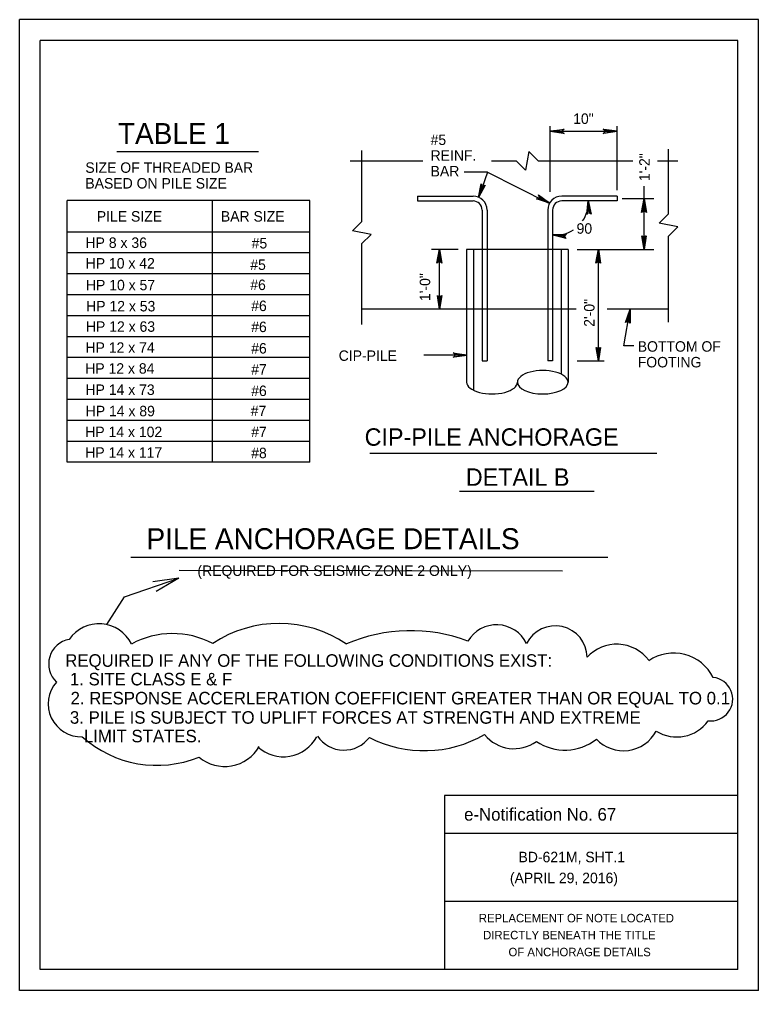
# Model space of a CAD drawing. Extents: x 235 to 2276, y 116 to 1308.
# Drawn here: x 274.6 to 486.6, y 1029.5 to 1307.9 of the extents above; entities that cross this region are included whole.
import ezdxf

# ---------------------------------------------------------------- set-up
doc = ezdxf.new("R2010")
doc.units = 0
doc.layers.add('1', color=7, linetype='Continuous')
doc.layers.add('2', color=7, linetype='Continuous')

msp = doc.modelspace()

# ---------------------------------------------------------------- linework, layer by layer
at = {"layer": '1'}
for p, q in [((426.86, 1258.51), (426.86, 1277.35)), ((426.86, 1275.86), (446.08, 1275.86)), ((446.08, 1259), (446.08, 1277.35)), ((343.24, 1270), (302.56, 1270)), ((372.72, 1270.33), (372.72, 1249.89)), ((420.78, 1270.01), (419.77, 1264.67)), ((423.54, 1267.25), (420.78, 1270.01)), ((460.71, 1270.76), (460.71, 1252.06)), ((390.35, 1267.25), (369.51, 1267.25)), ((417.19, 1267.25), (410.05, 1267.25)), ((419.77, 1264.67), (417.19, 1267.25)), ((450.59, 1267.25), (423.54, 1267.25)), ((463.48, 1267.25), (457.69, 1267.25)), ((408.89, 1264.16), (402.17, 1264.16)), ((408.89, 1264.16), (406.6, 1257.58)), ((408.89, 1264.16), (426.31, 1255.37)), ((453.86, 1241.99), (453.86, 1260.09)), ((357.95, 1255.96), (288.32, 1255.96)), ((288.32, 1180.96), (288.32, 1255.96)), ((330.05, 1180.96), (330.05, 1255.96)), ((357.95, 1180.96), (357.95, 1255.96)), ((388.85, 1257.27), (404.76, 1257.27)), ((388.85, 1257.27), (388.85, 1255.87)), ((388.85, 1255.87), (404.76, 1255.87)), ((446.08, 1257.27), (430.17, 1257.27)), ((446.08, 1255.87), (430.17, 1255.87)), ((446.08, 1257.27), (446.08, 1255.87)), ((456.55, 1256.52), (447.49, 1256.52)), ((407.36, 1253.27), (407.36, 1241.99)), ((408.76, 1253.27), (408.76, 1241.99)), ((426.17, 1253.27), (426.17, 1241.99)), ((427.57, 1253.27), (427.57, 1241.99)), ((458.13, 1249.48), (460.71, 1252.06)), ((370.14, 1247.31), (372.72, 1249.89)), ((375.49, 1246.3), (370.14, 1247.31)), ((463.47, 1248.47), (458.13, 1249.48)), ((460.71, 1245.71), (463.47, 1248.47)), ((357.95, 1246.96), (288.32, 1246.96)), ((372.72, 1243.54), (375.49, 1246.3)), ((460.71, 1245.71), (460.71, 1221.09)), ((372.72, 1243.54), (372.72, 1220.45)), ((400.52, 1241.99), (392.81, 1241.99)), ((395.13, 1224.86), (395.13, 1241.99)), ((432.02, 1241.99), (402.91, 1241.99)), ((402.91, 1241.99), (402.91, 1224.86)), ((404.88, 1241.99), (404.88, 1201.62)), ((407.36, 1241.99), (407.36, 1210.04)), ((408.76, 1241.99), (408.76, 1210.04)), ((426.17, 1241.99), (426.17, 1210.04)), ((427.57, 1241.99), (427.57, 1210.04)), ((430.05, 1241.99), (430.05, 1206.2)), ((432.02, 1241.99), (432.02, 1224.86)), ((434.61, 1241.99), (456.55, 1241.99)), ((440.69, 1210.04), (440.69, 1241.99)), ((357.95, 1240.96), (288.32, 1240.96)), ((357.95, 1234.96), (288.32, 1234.96)), ((357.95, 1228.96), (288.32, 1228.96)), ((357.95, 1222.96), (288.32, 1222.96)), ((434.31, 1224.86), (372.72, 1224.86)), ((402.91, 1224.86), (402.91, 1203.91)), ((432.02, 1224.86), (432.02, 1203.91)), ((460.7, 1224.86), (443.21, 1224.86)), ((447.95, 1214.36), (449.82, 1224.86)), ((357.95, 1216.96), (288.32, 1216.96)), ((450.86, 1214.36), (447.95, 1214.36)), ((402.91, 1211.69), (390.59, 1211.69)), ((357.95, 1210.96), (288.32, 1210.96)), ((407.36, 1210.04), (408.76, 1210.04)), ((427.57, 1210.04), (426.17, 1210.04)), ((434.61, 1210.04), (442.32, 1210.04)), ((357.95, 1204.96), (288.32, 1204.96)), ((357.95, 1198.96), (288.32, 1198.96)), ((357.95, 1192.96), (288.32, 1192.96)), ((357.95, 1186.96), (288.32, 1186.96)), ((375.18, 1183.61), (457.44, 1183.61)), ((357.95, 1180.96), (288.32, 1180.96)), ((439.49, 1172.59), (400.81, 1172.59)), ((306.6, 1153.79), (443.4, 1153.79)), ((320.48, 1150.03), (430.35, 1149.86)), ((304.79, 1142.42), (320.32, 1147.71)), ((320.32, 1147.71), (312.88, 1146.72)), ((320.32, 1147.71), (313.82, 1143.96)), ((299.66, 1134.49), (304.79, 1142.42))]:
    msp.add_line(p, q, dxfattribs=at)
for points in [[(430.58, 1275.35), (430.46, 1275.6), (426.83, 1275.85), (430.58, 1275.35), (430.83, 1275.23), (426.83, 1275.85), (430.46, 1275.98), (430.58, 1276.23), (426.83, 1275.85), (430.83, 1276.48), (430.58, 1276.23)], [(442.28, 1276.35), (442.41, 1276.1), (446.03, 1275.85), (442.28, 1276.35), (442.03, 1276.47), (446.03, 1275.85), (442.41, 1275.72), (442.28, 1275.35), (446.03, 1275.85), (442.03, 1275.22), (442.28, 1275.35)], [(408.02, 1260.26), (407.72, 1260.22), (406.33, 1256.85), (408.02, 1260.26), (408.24, 1260.39), (406.33, 1256.85), (407.35, 1260.34), (407.14, 1260.55), (406.33, 1256.85), (407.04, 1260.81), (407.14, 1260.55)], [(423.59, 1257.36), (423.59, 1257.06), (426.75, 1255.24), (423.59, 1257.36), (423.49, 1257.6), (426.75, 1255.24), (423.42, 1256.72), (423.18, 1256.53), (426.75, 1255.24), (422.92, 1256.46), (423.18, 1256.53)], [(437.51, 1252.19), (437.77, 1252.34), (437.77, 1255.98), (437.51, 1252.19), (437.35, 1251.98), (437.77, 1255.98), (438.15, 1252.36), (438.43, 1252.25), (437.77, 1255.98), (438.62, 1252.05), (438.43, 1252.25)], [(453.35, 1252.79), (453.6, 1252.92), (453.85, 1256.54), (453.35, 1252.79), (453.1, 1252.54), (453.85, 1256.54), (453.97, 1252.92), (454.22, 1252.79), (453.85, 1256.54), (454.47, 1252.54), (454.22, 1252.79)], [(431.24, 1245.27), (431.12, 1245.55), (427.53, 1246.13), (431.24, 1245.27), (431.41, 1245.08), (427.53, 1246.13), (431.16, 1245.93), (431.32, 1246.19), (427.53, 1246.13), (431.54, 1246.35), (431.32, 1246.19)], [(454.18, 1245.74), (453.93, 1245.61), (453.8, 1241.99), (454.18, 1245.74), (454.43, 1245.86), (453.8, 1241.99), (453.55, 1245.61), (453.3, 1245.74), (453.8, 1241.99), (453.18, 1245.86), (453.3, 1245.74)], [(394.63, 1238.32), (394.88, 1238.44), (395.13, 1242.07), (394.63, 1238.32), (394.38, 1238.07), (395.13, 1242.07), (395.25, 1238.44), (395.5, 1238.32), (395.13, 1242.07), (395.75, 1238.07), (395.5, 1238.32)], [(440.21, 1238.27), (440.46, 1238.4), (440.71, 1242.02), (440.21, 1238.27), (439.96, 1238.02), (440.71, 1242.02), (440.83, 1238.4), (441.08, 1238.27), (440.71, 1242.02), (441.33, 1238.02), (441.08, 1238.27)], [(395.52, 1228.61), (395.27, 1228.48), (395.14, 1224.86), (395.52, 1228.61), (395.77, 1228.73), (395.14, 1224.86), (394.89, 1228.48), (394.64, 1228.61), (395.14, 1224.86), (394.52, 1228.73), (394.64, 1228.61)], [(448.72, 1221.25), (448.98, 1221.33), (449.82, 1224.86), (448.72, 1221.25), (448.43, 1221.04), (449.82, 1224.86), (449.35, 1221.27), (449.58, 1221.1), (449.82, 1224.86), (449.79, 1220.81), (449.58, 1221.1)], [(441.09, 1213.77), (440.84, 1213.65), (440.71, 1210.02), (441.09, 1213.77), (441.34, 1213.9), (440.71, 1210.02), (440.46, 1213.65), (440.21, 1213.77), (440.71, 1210.02), (440.09, 1213.9), (440.21, 1213.77)], [(399.29, 1212.18), (399.41, 1211.93), (403.04, 1211.68), (399.29, 1212.18), (399.04, 1212.31), (403.04, 1211.68), (399.41, 1211.56), (399.29, 1211.18), (403.04, 1211.68), (399.04, 1211.06), (399.29, 1211.18)]]:
    msp.add_lwpolyline(points, dxfattribs=at)
for centre, radius, start, end in [((404.76, 1253.27), 4, 0, 90), ((404.76, 1253.27), 2.6, 0, 90), ((430.17, 1253.27), 4, 90, 180), ((430.17, 1253.27), 2.6, 90, 180), ((428.52, 1255.37), 9.27, 325.6533, 3.1394), ((428.52, 1255.37), 9.27, 264.1002, 302.8279), ((297.46, 1124.28), 10.38, 26.237, 145.2857), ((349.11, 1100.25), 34.51, 56.0176, 123.4882), ((411.5, 1124.77), 9.6, 26.3371, 149.1691), ((428.3, 1124.91), 9.17, 0.9811, 153.2557), ((318.57, 1107.03), 24.82, 62.4164, 118.3967), ((386.85, 1086.21), 46.48, 69.3272, 113.3892), ((290.17, 1123.16), 7.14, 100.0407, 226.8618), ((445.95, 1117.28), 11.52, 37.1351, 137.5112), ((462.27, 1113.49), 12.76, 26.9643, 123.9875), ((472.97, 1113.07), 6.24, 262.4602, 83.8615), ((292.29, 1111.68), 9.4, 138.1385, 272.2978), ((463.16, 1113.21), 11, 237.7444, 324.8871), ((390.77, 1132.82), 34.54, 242.8443, 300.0214), ((416.52, 1109.71), 10.86, 218.7414, 306.0613), ((447.85, 1109.01), 10.73, 223.7687, 331.573), ((314.05, 1126.02), 31.94, 227.9801, 292.2517), ((350.36, 1107.47), 10.93, 227.8208, 331.5044), ((367.69, 1107.61), 9.17, 214.4906, 322.962), ((431.06, 1113.02), 14.57, 236.0504, 308.3571), ((333.53, 1105.22), 11.45, 229.8927, 329.8905)]:
    msp.add_arc(centre, radius, start, end, dxfattribs=at)
for centre, major_axis, start_param, end_param in [((424.74, 1203.91), (7.28, 0), 0, 3.141598), ((410.19, 1203.91), (-7.28, 0), 0, 3.141593), ((424.74, 1203.91), (7.28, 0), 3.143175, 6.283185)]:
    msp.add_ellipse(centre, major_axis=major_axis, ratio=0.460563, start_param=start_param, end_param=end_param, dxfattribs=at)
at = {"layer": '2'}
for p, q in [((274.63, 1029.51), (274.63, 1307.91)), ((486.64, 1307.91), (274.63, 1307.91)), ((486.64, 1029.51), (486.64, 1307.91)), ((480.64, 1301.91), (280.63, 1301.91)), ((280.63, 1035.51), (280.63, 1301.91)), ((480.64, 1035.51), (480.64, 1301.91)), ((480.64, 1085.41), (396.59, 1085.41)), ((396.59, 1085.41), (396.59, 1035.51)), ((480.64, 1074.58), (396.59, 1074.58)), ((480.64, 1055.02), (396.59, 1055.02)), ((480.64, 1035.51), (280.63, 1035.51)), ((486.64, 1029.51), (274.63, 1029.51))]:
    msp.add_line(p, q, dxfattribs=at)

# ---------------------------------------------------------------- texts
at = {"layer": '1'}
for s, height, p in [('10"', 3.003, (433.45, 1277.95)), ('TABLE 1', 6, (302.9, 1272.21)), ('#5', 3, (392.56, 1271.91)), ('REINF.', 3, (392.56, 1267.41)), ('SIZE OF THREADED BAR', 3, (293.54, 1263.94)), ('BAR', 3, (392.56, 1262.91)), ('BASED ON PILE SIZE', 3, (293.54, 1259.44)), ('PILE SIZE', 3, (296.82, 1249.96)), ('BAR SIZE', 3, (332.41, 1249.96)), ('90', 3, (434.43, 1246.48)), ('HP 8 x 36', 3, (293.59, 1242.41)), ('#5', 3, (341.24, 1242.25)), ('HP 10 x 42', 3, (293.63, 1236.51)), ('#5', 3, (340.85, 1236.1)), ('#6', 3, (340.85, 1230.33)), ('HP 10 x 57', 3, (293.7, 1230.26)), ('HP 12 x 53', 3, (293.77, 1224.21)), ('#6', 3, (341.11, 1224.31)), ('HP 12 x 63', 3, (293.7, 1218.37)), ('#6', 3, (341.11, 1218.28)), ('HP 12 x 74', 3, (293.58, 1212.34)), ('#6', 3, (341.11, 1212.13)), ('BOTTOM OF', 3, (451.97, 1212.66)), ('CIP-PILE', 3, (366.21, 1210.03)), ('FOOTING', 3, (451.97, 1208.16)), ('HP 12 x 84', 3, (293.51, 1206.36)), ('#7', 3, (341.11, 1206.1)), ('HP 14 x 73', 3, (293.58, 1200.27)), ('#6', 3, (341.11, 1199.95)), ('HP 14 x 89', 3, (293.64, 1194.15)), ('#7', 3, (340.98, 1194.18)), ('HP 14 x 102', 3, (293.51, 1188.17)), ('#7', 3, (341.11, 1188.16)), (' CIP-PILE ANCHORAGE', 5, (371.79, 1185.7)), ('HP 14 x 117', 3, (293.51, 1182.26)), ('#8', 3, (341.11, 1182.13)), ('DETAIL B', 5, (402.67, 1174.22)), ('PILE ANCHORAGE DETAILS', 6, (311.08, 1156.05)), ('(REQUIRED FOR SEISMIC ZONE 2 ONLY)', 3, (325.68, 1148.38)), ('REQUIRED IF ANY OF THE FOLLOWING CONDITIONS EXIST:', 3.6, (287.78, 1122.33)), (' 1. SITE CLASS E & F', 3.6, (287.78, 1117)), (' 2. RESPONSE ACCERLERATION COEFFICIENT GREATER THAN OR EQUAL TO 0.1', 3.6, (287.98, 1111.55)), (' 3. PILE IS SUBJECT TO UPLIFT FORCES AT STRENGTH AND EXTREME ', 3.6, (287.78, 1106.01)), ('    LIMIT STATES.', 3.6, (287.78, 1100.68))]:
    msp.add_text(s, height=height, dxfattribs=at).set_placement(p)
for s, p in [('1\'-2"', (455.4, 1261.56)), ('1\'-0"', (392.45, 1227.18)), ('2\'-0"', (439.58, 1219.8))]:
    msp.add_text(s, height=3, rotation=90, dxfattribs=at).set_placement(p)
at = {"layer": '2'}
for s, height, p in [('e-Notification No. 67', 3.6, (402.18, 1078.23)), ('BD-621M, SHT.1', 3, (417.77, 1066.3)), ('(APRIL 29, 2016)', 3, (415.31, 1060.3)), ('REPLACEMENT OF NOTE LOCATED', 2.43, (406.4, 1049.07)), ('DIRECTLY BENEATH THE TITLE', 2.43, (407.62, 1044.21)), ('OF ANCHORAGE DETAILS', 2.43, (414.91, 1039.35))]:
    msp.add_text(s, height=height, dxfattribs=at).set_placement(p)

doc.saveas('drawing.dxf')
